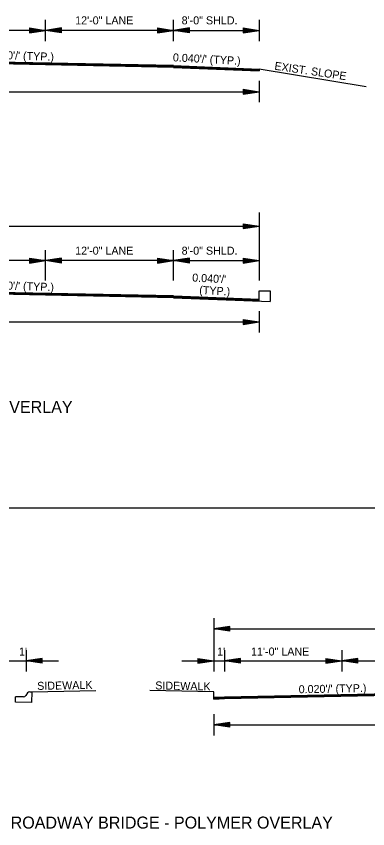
# Model space of a CAD drawing. Extents: x 550980 to 1930787, y -1972975 to 596640.
# Drawn here: x 551662 to 551991, y -1957794 to -1957033 of the extents above; entities that cross this region are included whole.
import ezdxf

# ---------------------------------------------------------------- set-up
doc = ezdxf.new("R2010")
doc.units = 0
doc.layers.add('R_Border', color=7, linetype='Continuous')
doc.layers.add('R_Draft', color=7, linetype='Continuous')

msp = doc.modelspace()

# ---------------------------------------------------------------- linework, layer by layer
at = {"layer": 'R_Border'}
for p, q in [((551889.87, -1957299.65), (551889.87, -1957290.24)), ((551889.87, -1957290.24), (551900.04, -1957290.24)), ((551900.04, -1957290.24), (551900.04, -1957300.25)), ((551005.61, -1957493.51), (552066.88, -1957493.51)), ((551847.2, -1957596.84), (551847.2, -1957646.84)), ((551862.2, -1957604.59), (551847.2, -1957606.84)), ((551847.2, -1957606.84), (552427.2, -1957606.84)), ((551862.2, -1957609.09), (551847.2, -1957606.84)), ((551862.2, -1957604.97), (551849.71, -1957606.84)), ((551862.2, -1957608.72), (551849.71, -1957606.84)), ((551862.2, -1957605.35), (551852.29, -1957606.84)), ((551862.2, -1957608.33), (551852.29, -1957606.84)), ((551862.2, -1957605.72), (551854.78, -1957606.84)), ((551862.2, -1957607.96), (551854.78, -1957606.84)), ((551862.2, -1957606.11), (551857.33, -1957606.84)), ((551862.2, -1957607.57), (551857.33, -1957606.84)), ((551862.2, -1957606.49), (551859.83, -1957606.84)), ((551862.2, -1957607.19), (551859.83, -1957606.84)), ((551862.2, -1957609.09), (551862.2, -1957604.59)), ((551671.65, -1957626.84), (551671.65, -1957646.84)), ((551857.2, -1957626.84), (551857.2, -1957646.84)), ((551967.2, -1957626.84), (551967.2, -1957646.84)), ((551061.65, -1957636.84), (551701.65, -1957636.84)), ((551686.65, -1957634.59), (551671.65, -1957636.84)), ((551686.65, -1957639.09), (551671.65, -1957636.84)), ((551686.65, -1957634.97), (551674.15, -1957636.84)), ((551686.65, -1957638.72), (551674.15, -1957636.84)), ((551686.65, -1957635.35), (551676.73, -1957636.84)), ((551686.65, -1957638.33), (551676.73, -1957636.84)), ((551686.65, -1957635.72), (551679.23, -1957636.84)), ((551686.65, -1957637.96), (551679.23, -1957636.84)), ((551686.65, -1957636.11), (551681.77, -1957636.84)), ((551686.65, -1957637.57), (551681.77, -1957636.84)), ((551686.65, -1957636.49), (551684.28, -1957636.84)), ((551686.65, -1957637.19), (551684.28, -1957636.84)), ((551686.65, -1957639.09), (551686.65, -1957634.59)), ((551817.2, -1957636.84), (552457.2, -1957636.84)), ((551832.2, -1957634.59), (551847.2, -1957636.84)), ((551832.2, -1957634.59), (551832.2, -1957639.09)), ((551832.2, -1957634.97), (551844.7, -1957636.84)), ((551832.2, -1957635.35), (551842.12, -1957636.84)), ((551832.2, -1957635.72), (551839.62, -1957636.84)), ((551832.2, -1957636.11), (551837.08, -1957636.84)), ((551832.2, -1957636.49), (551834.57, -1957636.84)), ((551832.2, -1957639.09), (551847.2, -1957636.84)), ((551832.2, -1957637.58), (551837.08, -1957636.84)), ((551832.2, -1957638.33), (551842.12, -1957636.84)), ((551832.2, -1957638.72), (551844.7, -1957636.84)), ((551832.2, -1957637.96), (551839.62, -1957636.84)), ((551832.2, -1957637.19), (551834.57, -1957636.84)), ((551872.2, -1957634.59), (551857.2, -1957636.84)), ((551872.2, -1957639.09), (551857.2, -1957636.84)), ((551872.2, -1957634.97), (551859.71, -1957636.84)), ((551872.2, -1957638.72), (551859.71, -1957636.84)), ((551872.2, -1957635.35), (551862.29, -1957636.84)), ((551872.2, -1957638.33), (551862.29, -1957636.84)), ((551872.2, -1957635.72), (551864.78, -1957636.84)), ((551872.2, -1957637.96), (551864.78, -1957636.84)), ((551872.2, -1957636.11), (551867.33, -1957636.84)), ((551872.2, -1957637.57), (551867.33, -1957636.84)), ((551872.2, -1957636.49), (551869.83, -1957636.84)), ((551872.2, -1957637.19), (551869.83, -1957636.84)), ((551872.2, -1957639.09), (551872.2, -1957634.59)), ((551952.2, -1957634.59), (551967.2, -1957636.84)), ((551952.2, -1957634.59), (551952.2, -1957639.09)), ((551952.2, -1957634.97), (551964.7, -1957636.84)), ((551952.2, -1957635.35), (551962.12, -1957636.84)), ((551952.2, -1957635.72), (551959.62, -1957636.84)), ((551952.2, -1957636.11), (551957.08, -1957636.84)), ((551952.2, -1957636.49), (551954.57, -1957636.84)), ((551952.2, -1957639.09), (551967.2, -1957636.84)), ((551952.2, -1957637.58), (551957.08, -1957636.84)), ((551952.2, -1957638.33), (551962.12, -1957636.84)), ((551952.2, -1957638.72), (551964.7, -1957636.84)), ((551952.2, -1957637.96), (551959.62, -1957636.84)), ((551952.2, -1957637.19), (551954.57, -1957636.84)), ((551982.2, -1957634.59), (551967.2, -1957636.84)), ((551982.2, -1957639.09), (551967.2, -1957636.84)), ((551982.2, -1957634.97), (551969.71, -1957636.84)), ((551982.2, -1957638.72), (551969.71, -1957636.84)), ((551982.2, -1957635.35), (551972.29, -1957636.84)), ((551982.2, -1957638.33), (551972.29, -1957636.84)), ((551982.2, -1957635.72), (551974.78, -1957636.84)), ((551982.2, -1957637.96), (551974.78, -1957636.84)), ((551982.2, -1957636.11), (551977.33, -1957636.84)), ((551982.2, -1957637.57), (551977.33, -1957636.84)), ((551982.2, -1957636.49), (551979.83, -1957636.84)), ((551982.2, -1957637.19), (551979.83, -1957636.84)), ((551982.2, -1957639.09), (551982.2, -1957634.59)), ((551676.74, -1957665.74), (551736.74, -1957664.54)), ((551847.2, -1957686.84), (551847.2, -1957706.84)), ((551862.2, -1957694.59), (551847.2, -1957696.84)), ((551847.2, -1957696.84), (552427.2, -1957696.84)), ((551862.2, -1957699.09), (551847.2, -1957696.84)), ((551862.2, -1957694.97), (551849.71, -1957696.84)), ((551862.2, -1957698.72), (551849.71, -1957696.84)), ((551862.2, -1957695.35), (551852.29, -1957696.84)), ((551862.2, -1957698.33), (551852.29, -1957696.84)), ((551862.2, -1957695.72), (551854.78, -1957696.84)), ((551862.2, -1957697.96), (551854.78, -1957696.84)), ((551862.2, -1957696.11), (551857.33, -1957696.84)), ((551862.2, -1957697.57), (551857.33, -1957696.84)), ((551862.2, -1957696.49), (551859.83, -1957696.84)), ((551862.2, -1957697.19), (551859.83, -1957696.84)), ((551862.2, -1957699.09), (551862.2, -1957694.59))]:
    msp.add_line(p, q, dxfattribs=at)
for points in [[(551847.2, -1957672.64), (551847.2, -1957665.84), (551787.2, -1957664.64), (551787.2, -1957664.64)], [(551847.2, -1957670.84), (551857.2, -1957670.44), (552137.2, -1957664.84), (552417.2, -1957670.44), (552427.2, -1957670.84)], [(551847.2, -1957671.14), (551857.2, -1957670.74), (552137.2, -1957665.14), (552417.2, -1957670.74), (552427.2, -1957671.14)], [(551847.2, -1957671.44), (551857.2, -1957671.04), (552137.2, -1957665.44), (552417.2, -1957671.04), (552427.2, -1957671.44)], [(551847.2, -1957671.74), (551857.2, -1957671.34), (552137.2, -1957665.74), (552417.2, -1957671.34), (552427.2, -1957671.74)], [(551847.2, -1957672.04), (551857.2, -1957671.64), (552137.2, -1957666.04), (552417.2, -1957671.64), (552427.2, -1957672.04)], [(551847.2, -1957672.34), (551857.2, -1957671.94), (552137.2, -1957666.34), (552417.2, -1957671.94), (552427.2, -1957672.34)], [(551847.2, -1957672.64), (551857.2, -1957672.24), (552137.2, -1957666.64), (552417.2, -1957672.24), (552427.2, -1957672.64)]]:
    msp.add_lwpolyline(points, dxfattribs=at)
at = {"layer": 'R_Draft'}
for p, q in [((551689.61, -1957056.17), (551689.61, -1957036.28)), ((551809.61, -1957056.17), (551809.61, -1957036.28)), ((551689.61, -1957046.17), (551569.61, -1957046.17)), ((551674.61, -1957043.92), (551689.61, -1957046.17)), ((551674.61, -1957043.92), (551674.61, -1957048.42)), ((551674.61, -1957044.3), (551687.1, -1957046.17)), ((551674.61, -1957044.68), (551684.52, -1957046.17)), ((551674.61, -1957045.06), (551682.03, -1957046.17)), ((551674.61, -1957045.45), (551679.48, -1957046.17)), ((551674.61, -1957045.82), (551676.98, -1957046.17)), ((551674.61, -1957048.42), (551689.61, -1957046.17)), ((551674.61, -1957046.91), (551679.48, -1957046.17)), ((551674.61, -1957047.67), (551684.52, -1957046.17)), ((551674.61, -1957048.05), (551687.1, -1957046.17)), ((551674.61, -1957047.29), (551682.03, -1957046.17)), ((551674.61, -1957046.53), (551676.98, -1957046.17)), ((551704.61, -1957043.92), (551689.61, -1957046.17)), ((551704.61, -1957048.42), (551689.61, -1957046.17)), ((551809.61, -1957046.17), (551689.61, -1957046.17)), ((551704.61, -1957044.3), (551692.11, -1957046.17)), ((551704.61, -1957048.05), (551692.11, -1957046.17)), ((551704.61, -1957044.68), (551694.69, -1957046.17)), ((551704.61, -1957047.67), (551694.69, -1957046.17)), ((551704.61, -1957045.06), (551697.19, -1957046.17)), ((551704.61, -1957047.29), (551697.19, -1957046.17)), ((551704.61, -1957045.44), (551699.73, -1957046.17)), ((551704.61, -1957046.9), (551699.73, -1957046.17)), ((551704.61, -1957045.82), (551702.24, -1957046.17)), ((551704.61, -1957046.53), (551702.24, -1957046.17)), ((551704.61, -1957048.42), (551704.61, -1957043.92)), ((551794.61, -1957043.92), (551809.61, -1957046.17)), ((551794.61, -1957043.92), (551794.61, -1957048.42)), ((551794.61, -1957044.3), (551807.1, -1957046.17)), ((551794.61, -1957044.68), (551804.52, -1957046.17)), ((551794.61, -1957045.06), (551802.03, -1957046.17)), ((551794.61, -1957045.45), (551799.48, -1957046.17)), ((551794.61, -1957045.82), (551796.98, -1957046.17)), ((551794.61, -1957048.42), (551809.61, -1957046.17)), ((551794.61, -1957046.91), (551799.48, -1957046.17)), ((551794.61, -1957047.67), (551804.52, -1957046.17)), ((551794.61, -1957048.05), (551807.1, -1957046.17)), ((551794.61, -1957047.29), (551802.03, -1957046.17)), ((551794.61, -1957046.53), (551796.98, -1957046.17)), ((551824.61, -1957043.92), (551809.61, -1957046.17)), ((551809.61, -1957046.17), (551889.61, -1957046.17)), ((551824.61, -1957048.42), (551809.61, -1957046.17)), ((551824.61, -1957044.3), (551812.11, -1957046.17)), ((551824.61, -1957048.05), (551812.11, -1957046.17)), ((551824.61, -1957044.68), (551814.69, -1957046.17)), ((551824.61, -1957047.67), (551814.69, -1957046.17)), ((551824.61, -1957045.06), (551817.19, -1957046.17)), ((551824.61, -1957047.29), (551817.19, -1957046.17)), ((551824.61, -1957045.44), (551819.73, -1957046.17)), ((551824.61, -1957046.9), (551819.73, -1957046.17)), ((551824.61, -1957045.82), (551822.24, -1957046.17)), ((551824.61, -1957046.53), (551822.24, -1957046.17)), ((551824.61, -1957048.42), (551824.61, -1957043.92)), ((551874.61, -1957043.92), (551889.61, -1957046.17)), ((551874.61, -1957043.92), (551874.61, -1957048.42)), ((551874.61, -1957044.3), (551887.1, -1957046.17)), ((551874.61, -1957044.68), (551884.52, -1957046.17)), ((551874.61, -1957045.06), (551882.03, -1957046.17)), ((551874.61, -1957045.45), (551879.48, -1957046.17)), ((551874.61, -1957045.82), (551876.98, -1957046.17)), ((551874.61, -1957048.42), (551889.61, -1957046.17)), ((551874.61, -1957046.91), (551879.48, -1957046.17)), ((551874.61, -1957047.67), (551884.52, -1957046.17)), ((551874.61, -1957048.05), (551887.1, -1957046.17)), ((551874.61, -1957047.29), (551882.03, -1957046.17)), ((551874.61, -1957046.53), (551876.98, -1957046.17)), ((551809.61, -1957079.48), (551539.6, -1957074.08)), ((551809.61, -1957079.18), (551539.61, -1957073.78)), ((551809.61, -1957080.88), (551539.57, -1957075.48)), ((551809.61, -1957080.38), (551539.58, -1957074.98)), ((551809.61, -1957080.68), (551539.58, -1957075.28)), ((551809.61, -1957080.08), (551539.59, -1957074.68)), ((551809.61, -1957079.78), (551539.6, -1957074.38)), ((551809.54, -1957080.88), (551889.88, -1957084.09)), ((551809.55, -1957080.68), (551889.87, -1957083.89)), ((551809.56, -1957080.38), (551889.87, -1957083.59)), ((551809.57, -1957080.08), (551889.87, -1957083.29)), ((551809.58, -1957079.78), (551889.87, -1957082.99)), ((551809.6, -1957079.48), (551889.87, -1957082.69)), ((551809.61, -1957079.18), (551889.87, -1957082.39)), ((551989.94, -1957099.07), (551889.87, -1957082.39)), ((551889.87, -1957082.39), (551889.87, -1957084.09)), ((551889.61, -1957093.39), (551889.61, -1957113.39)), ((551189.57, -1957103.64), (551889.61, -1957103.64)), ((551874.61, -1957101.39), (551889.61, -1957103.64)), ((551874.61, -1957101.39), (551874.61, -1957105.89)), ((551874.61, -1957101.76), (551887.1, -1957103.64)), ((551874.61, -1957102.14), (551884.52, -1957103.64)), ((551874.61, -1957102.52), (551882.03, -1957103.64)), ((551874.61, -1957102.91), (551879.48, -1957103.64)), ((551874.61, -1957103.28), (551876.98, -1957103.64)), ((551874.61, -1957105.89), (551889.61, -1957103.64)), ((551874.61, -1957104.37), (551879.48, -1957103.64)), ((551874.61, -1957105.13), (551884.52, -1957103.64)), ((551874.61, -1957105.51), (551887.1, -1957103.64)), ((551874.61, -1957104.75), (551882.03, -1957103.64)), ((551874.61, -1957103.99), (551876.98, -1957103.64)), ((551189.57, -1957229.57), (551889.61, -1957229.57)), ((551874.64, -1957227.32), (551889.64, -1957229.57)), ((551874.64, -1957227.32), (551874.64, -1957231.82)), ((551874.64, -1957227.69), (551887.14, -1957229.57)), ((551874.64, -1957228.08), (551884.56, -1957229.57)), ((551874.64, -1957228.45), (551882.06, -1957229.57)), ((551874.64, -1957228.84), (551879.52, -1957229.57)), ((551874.64, -1957229.22), (551877.01, -1957229.57)), ((551874.64, -1957231.82), (551889.64, -1957229.57)), ((551874.64, -1957230.3), (551879.52, -1957229.57)), ((551874.64, -1957231.06), (551884.56, -1957229.57)), ((551874.64, -1957231.44), (551887.14, -1957229.57)), ((551874.64, -1957230.69), (551882.06, -1957229.57)), ((551874.64, -1957229.92), (551877.01, -1957229.57)), ((551689.61, -1957280.58), (551689.61, -1957252.03)), ((551809.61, -1957280.58), (551809.61, -1957252.03)), ((551689.61, -1957261.93), (551569.61, -1957261.93)), ((551674.61, -1957259.68), (551689.61, -1957261.93)), ((551674.61, -1957259.68), (551674.61, -1957264.18)), ((551674.61, -1957260.05), (551687.1, -1957261.93)), ((551674.61, -1957260.44), (551684.52, -1957261.93)), ((551674.61, -1957260.81), (551682.03, -1957261.93)), ((551674.61, -1957261.2), (551679.48, -1957261.93)), ((551674.61, -1957261.58), (551676.98, -1957261.93)), ((551674.61, -1957264.18), (551689.61, -1957261.93)), ((551674.61, -1957262.66), (551679.48, -1957261.93)), ((551674.61, -1957263.42), (551684.52, -1957261.93)), ((551674.61, -1957263.8), (551687.1, -1957261.93)), ((551674.61, -1957263.05), (551682.03, -1957261.93)), ((551674.61, -1957262.28), (551676.98, -1957261.93)), ((551704.61, -1957259.68), (551689.61, -1957261.93)), ((551704.61, -1957264.18), (551689.61, -1957261.93)), ((551809.61, -1957261.93), (551689.61, -1957261.93)), ((551704.61, -1957260.05), (551692.11, -1957261.93)), ((551704.61, -1957263.8), (551692.11, -1957261.93)), ((551704.61, -1957260.44), (551694.69, -1957261.93)), ((551704.61, -1957263.42), (551694.69, -1957261.93)), ((551704.61, -1957260.81), (551697.19, -1957261.93)), ((551704.61, -1957263.05), (551697.19, -1957261.93)), ((551704.61, -1957261.19), (551699.73, -1957261.93)), ((551704.61, -1957262.66), (551699.73, -1957261.93)), ((551704.61, -1957261.58), (551702.24, -1957261.93)), ((551704.61, -1957262.28), (551702.24, -1957261.93)), ((551704.61, -1957264.18), (551704.61, -1957259.68)), ((551794.61, -1957259.68), (551809.61, -1957261.93)), ((551794.61, -1957259.68), (551794.61, -1957264.18)), ((551794.61, -1957260.05), (551807.1, -1957261.93)), ((551794.61, -1957260.44), (551804.52, -1957261.93)), ((551794.61, -1957260.81), (551802.03, -1957261.93)), ((551794.61, -1957261.2), (551799.48, -1957261.93)), ((551794.61, -1957261.58), (551796.98, -1957261.93)), ((551794.61, -1957264.18), (551809.61, -1957261.93)), ((551794.61, -1957262.66), (551799.48, -1957261.93)), ((551794.61, -1957263.42), (551804.52, -1957261.93)), ((551794.61, -1957263.8), (551807.1, -1957261.93)), ((551794.61, -1957263.05), (551802.03, -1957261.93)), ((551794.61, -1957262.28), (551796.98, -1957261.93)), ((551824.61, -1957259.68), (551809.61, -1957261.93)), ((551809.61, -1957261.93), (551889.61, -1957261.93)), ((551824.61, -1957264.18), (551809.61, -1957261.93)), ((551824.61, -1957260.05), (551812.11, -1957261.93)), ((551824.61, -1957263.8), (551812.11, -1957261.93)), ((551824.61, -1957260.44), (551814.69, -1957261.93)), ((551824.61, -1957263.42), (551814.69, -1957261.93)), ((551824.61, -1957260.81), (551817.19, -1957261.93)), ((551824.61, -1957263.05), (551817.19, -1957261.93)), ((551824.61, -1957261.19), (551819.73, -1957261.93)), ((551824.61, -1957262.66), (551819.73, -1957261.93)), ((551824.61, -1957261.58), (551822.24, -1957261.93)), ((551824.61, -1957262.28), (551822.24, -1957261.93)), ((551824.61, -1957264.18), (551824.61, -1957259.68)), ((551874.61, -1957259.68), (551889.61, -1957261.93)), ((551874.61, -1957259.68), (551874.61, -1957264.18)), ((551874.61, -1957260.05), (551887.1, -1957261.93)), ((551874.61, -1957260.44), (551884.52, -1957261.93)), ((551874.61, -1957260.81), (551882.03, -1957261.93)), ((551874.61, -1957261.2), (551879.48, -1957261.93)), ((551874.61, -1957261.58), (551876.98, -1957261.93)), ((551874.61, -1957264.18), (551889.61, -1957261.93)), ((551874.61, -1957262.66), (551879.48, -1957261.93)), ((551874.61, -1957263.42), (551884.52, -1957261.93)), ((551874.61, -1957263.8), (551887.1, -1957261.93)), ((551874.61, -1957263.05), (551882.03, -1957261.93)), ((551874.61, -1957262.28), (551876.98, -1957261.93)), ((551809.61, -1957296.63), (551539.57, -1957291.23)), ((551809.61, -1957296.13), (551539.58, -1957290.73)), ((551809.61, -1957296.43), (551539.58, -1957291.03)), ((551809.61, -1957295.83), (551539.59, -1957290.43)), ((551809.61, -1957295.23), (551539.6, -1957289.83)), ((551809.61, -1957295.53), (551539.6, -1957290.13)), ((551809.61, -1957294.93), (551539.61, -1957289.53)), ((551809.61, -1957294.93), (551889.87, -1957298.14)), ((551809.54, -1957296.63), (551900.04, -1957300.25)), ((551809.55, -1957296.43), (551889.87, -1957299.65)), ((551809.56, -1957296.13), (551889.87, -1957299.35)), ((551809.57, -1957295.83), (551889.87, -1957299.04)), ((551809.58, -1957295.53), (551889.87, -1957298.74)), ((551809.6, -1957295.23), (551889.87, -1957298.44)), ((551889.61, -1957309.14), (551889.61, -1957329.14)), ((551874.61, -1957317.14), (551889.61, -1957319.39)), ((551874.61, -1957317.14), (551874.61, -1957321.64)), ((551874.61, -1957317.52), (551887.1, -1957319.39)), ((551189.57, -1957319.39), (551889.61, -1957319.39)), ((551874.61, -1957317.9), (551884.52, -1957319.39)), ((551874.61, -1957318.27), (551882.03, -1957319.39)), ((551874.61, -1957318.66), (551879.48, -1957319.39)), ((551874.61, -1957319.04), (551876.98, -1957319.39)), ((551874.61, -1957321.64), (551889.61, -1957319.39)), ((551874.61, -1957320.13), (551879.48, -1957319.39)), ((551874.61, -1957320.88), (551884.52, -1957319.39)), ((551874.61, -1957321.27), (551887.1, -1957319.39)), ((551874.61, -1957320.51), (551882.03, -1957319.39)), ((551874.61, -1957319.74), (551876.98, -1957319.39)), ((551672.81, -1957666.92), (551671.34, -1957669.38)), ((551675.01, -1957665.71), (551676.74, -1957665.74)), ((551669.15, -1957670.59), (551661.65, -1957670.44))]:
    msp.add_line(p, q, dxfattribs=at)
for points in [[(551889.61, -1957036.17), (551889.61, -1957056.17)], [(551889.61, -1957216.96), (551889.61, -1957280.58)], [(551676.74, -1957665.74), (551676.54, -1957675.74), (551661.65, -1957675.44), (551661.65, -1957670.44)]]:
    msp.add_lwpolyline(points, dxfattribs=at)
for centre, start, end in [((551674.96, -1957668.21), 88.85424, 149.05595), ((551669.2, -1957668.09), 268.85424, 329.05595)]:
    msp.add_arc(centre, 2.5, start, end, dxfattribs=at)

# ---------------------------------------------------------------- texts
at = {"layer": 'R_Border'}
for s, height, p in [("1'", 7.5, (551664.82, -1957631.84)), ("1'", 7.5, (551850.37, -1957631.84)), ('11\'-0" LANE', 7.5, (551882.14, -1957631.84)), ('58 FT. CLEAR ROADWAY BRIDGE - POLYMER OVERLAY', 11.25, (551554.97, -1957793.97))]:
    msp.add_text(s, height=height, dxfattribs=at).set_placement(p)
for s, rotation, p in [('SIDEWALK', 1.1458, (551681.89, -1957664.08)), ('SIDEWALK', 358.8542, (551792.34, -1957663.56)), ("0.020'/' (TYP.)", 1.1458, (551926.81, -1957667.25))]:
    msp.add_text(s, height=7.5, rotation=rotation, dxfattribs=at).set_placement(p)
at = {"layer": 'R_Draft'}
for s, height, p in [('12\'-0" LANE', 7.5, (551717.42, -1957040.57)), ('8\'-0" SHLD.', 7.5, (551817.13, -1957040.57)), ('12\'-0" LANE', 7.5, (551717.42, -1957256.33)), ('8\'-0" SHLD.', 7.5, (551817.13, -1957256.33)), ('70 FT. CLEAR ROADWAY BRIDGE - POLYMER OVERLAY', 11.25, (551311.24, -1957404.62))]:
    msp.add_text(s, height=height, dxfattribs=at).set_placement(p)
for s, rotation, p in [("0.020'/' (TYP.)", 358.06067, (551633.97, -1957072.56)), ("0.040'/' (TYP.)", 356.93347, (551808.78, -1957075.14)), ('EXIST. SLOPE', 351.57554, (551903.69, -1957082.95)), ("0.040'/' ", 356.93347, (551826.89, -1957281.42)), ("0.020'/' (TYP.)", 358.06067, (551633.97, -1957288.31)), ('(TYP.)', 356.93347, (551833.48, -1957293.04))]:
    msp.add_text(s, height=7.5, rotation=rotation, dxfattribs=at).set_placement(p)

doc.saveas('drawing.dxf')
